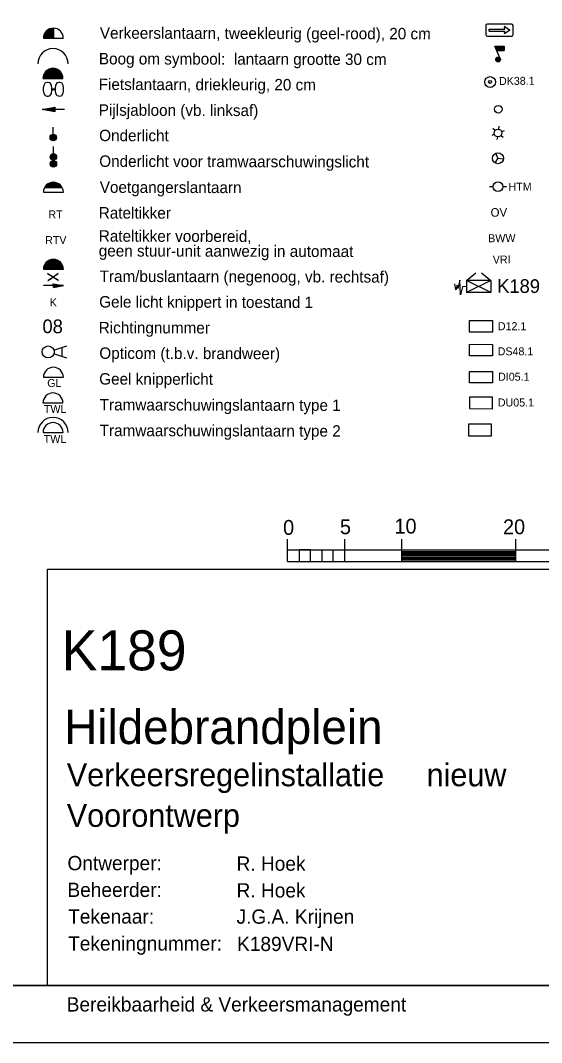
# Model space of a CAD drawing. Extents: x 81065 to 81486, y 452384 to 452681.
# Drawn here: x 81384.6 to 81430.3, y 452383.5 to 452473.1 of the extents above; entities that cross this region are included whole.
import ezdxf

# ---------------------------------------------------------------- set-up
doc = ezdxf.new("R2010")
doc.units = 0
for name, color, linetype in [('X-XX-AL-TEKENBLAD-S', 7, 'Continuous'), ('X-XX-AL-TEKENBLAD_KADER-G', 7, 'Continuous'), ('X-XX-AL-TEKENBLAD_KADER_AFSNIJMARKERING-G', 7, 'Continuous'), ('X-XX-AL-TEKENBLAD_VERKLARING-T70', 7, 'Continuous'), ('X-XX-AL-TEKENBLAD_VIEWPORT-G', 7, 'Continuous')]:
    doc.layers.add(name, color=color, linetype=linetype)

msp = doc.modelspace()

# ---------------------------------------------------------------- linework, layer by layer
at = {"layer": 'X-XX-AL-TEKENBLAD-S'}
for p, q in [((81408.052, 452425.679), (81408.05, 452427.626)), ((81413.05, 452425.679), (81413.05, 452427.626)), ((81418.05, 452425.679), (81418.05, 452427.626)), ((81428.05, 452425.679), (81428.05, 452427.626)), ((81408.053, 452426.679), (81458.05, 452426.679)), ((81410.05, 452426.679), (81409.05, 452426.679)), ((81409.05, 452426.679), (81409.05, 452425.679)), ((81410.05, 452425.679), (81410.05, 452426.679)), ((81411.05, 452426.679), (81411.05, 452425.679)), ((81412.05, 452425.679), (81412.05, 452426.679)), ((81418.05, 452426.553), (81428.05, 452426.553)), ((81418.05, 452426.429), (81428.05, 452426.429)), ((81408.053, 452425.679), (81458.05, 452425.679)), ((81418.05, 452426.303), (81428.05, 452426.303)), ((81418.05, 452426.179), (81428.05, 452426.179)), ((81418.05, 452426.053), (81428.05, 452426.053)), ((81418.05, 452425.929), (81428.05, 452425.929)), ((81418.05, 452425.803), (81428.05, 452425.803)), ((81418.05, 452425.679), (81428.05, 452425.679)), ((81387.021, 452388.532), (81387.021, 452424.987)), ((81387.021, 452424.987), (81480.708, 452424.987)), ((81387.021, 452388.532), (81480.708, 452388.532))]:
    msp.add_line(p, q, dxfattribs=at)
at = {"layer": 'X-XX-AL-TEKENBLAD_KADER-G'}
msp.add_lwpolyline([(81480.708, 452388.532), (81070.22, 452388.532), (81070.22, 452675.532), (81480.708, 452675.532)], close=True, dxfattribs=at)
at = {"layer": 'X-XX-AL-TEKENBLAD_KADER_AFSNIJMARKERING-G'}
msp.add_lwpolyline([(81485.714, 452680.532), (81065.214, 452680.532), (81065.214, 452383.532), (81485.714, 452383.532)], close=True, dxfattribs=at)
at = {"layer": 'X-XX-AL-TEKENBLAD_VERKLARING-T70'}
for p, q in [((81386.804, 452471.992), (81387.533, 452471.993)), ((81386.824, 452472.023), (81387.532, 452472.023)), ((81386.848, 452472.053), (81387.535, 452472.053)), ((81386.87, 452472.083), (81387.532, 452472.083)), ((81386.899, 452472.112), (81387.533, 452472.112)), ((81386.929, 452472.143), (81387.535, 452472.143)), ((81386.96, 452472.173), (81387.532, 452472.173)), ((81386.999, 452472.205), (81387.533, 452472.205)), ((81387.038, 452472.233), (81387.533, 452472.235)), ((81387.088, 452472.265), (81387.533, 452472.265)), ((81387.14, 452472.293), (81387.533, 452472.295)), ((81387.208, 452472.323), (81387.532, 452472.325)), ((81387.296, 452472.353), (81387.535, 452472.355)), ((81387.47, 452472.383), (81387.533, 452472.385)), ((81387.533, 452472.386), (81387.532, 452471.513)), ((81425.411, 452472.603), (81425.411, 452471.814)), ((81427.652, 452472.743), (81425.551, 452472.743)), ((81425.694, 452472.13), (81425.699, 452472.282)), ((81425.694, 452472.13), (81427.084, 452472.132)), ((81425.699, 452472.282), (81427.082, 452472.284)), ((81427.082, 452472.284), (81427.037, 452472.485)), ((81427.038, 452471.934), (81427.084, 452472.132)), ((81427.083, 452472.516), (81427.492, 452472.233)), ((81427.492, 452472.184), (81427.084, 452471.902)), ((81427.496, 452472.187), (81427.496, 452472.187)), ((81427.796, 452471.809), (81427.792, 452472.603)), ((81386.66, 452471.543), (81387.533, 452471.543)), ((81386.66, 452471.513), (81388.408, 452471.513)), ((81386.662, 452471.573), (81387.532, 452471.575)), ((81386.665, 452471.603), (81387.533, 452471.605)), ((81386.668, 452471.633), (81387.533, 452471.635)), ((81386.674, 452471.665), (81387.533, 452471.663)), ((81386.678, 452471.693), (81387.533, 452471.693)), ((81386.684, 452471.722), (81387.533, 452471.723)), ((81386.695, 452471.755), (81387.533, 452471.753)), ((81386.702, 452471.783), (81387.535, 452471.783)), ((81386.713, 452471.813), (81387.533, 452471.813)), ((81386.723, 452471.843), (81387.532, 452471.843)), ((81386.737, 452471.873), (81387.535, 452471.873)), ((81386.753, 452471.902), (81387.533, 452471.902)), ((81386.767, 452471.933), (81387.532, 452471.933)), ((81386.785, 452471.963), (81387.535, 452471.963)), ((81425.55, 452471.674), (81427.655, 452471.669)), ((81426.672, 452469.737), (81426.189, 452470.798)), ((81426.189, 452470.798), (81427.006, 452470.798)), ((81426.192, 452470.787), (81427.006, 452470.787)), ((81426.201, 452470.766), (81427.006, 452470.765)), ((81426.213, 452470.744), (81427.006, 452470.744)), ((81426.223, 452470.723), (81427.006, 452470.72)), ((81426.232, 452470.7), (81427.006, 452470.7)), ((81426.244, 452470.681), (81427.006, 452470.679)), ((81426.253, 452470.658), (81427.006, 452470.657)), ((81426.264, 452470.636), (81427.005, 452470.636)), ((81426.273, 452470.613), (81427.006, 452470.613)), ((81426.283, 452470.592), (81427.006, 452470.592)), ((81426.292, 452470.571), (81427.008, 452470.57)), ((81426.303, 452470.549), (81427.006, 452470.549)), ((81426.312, 452470.528), (81427.005, 452470.526)), ((81426.322, 452470.505), (81427.006, 452470.505)), ((81426.331, 452470.484), (81427.006, 452470.483)), ((81426.342, 452470.463), (81427.006, 452470.462)), ((81426.352, 452470.441), (81427.008, 452470.439)), ((81426.361, 452470.418), (81427.006, 452470.417)), ((81427.006, 452470.798), (81427.006, 452470.417)), ((81386.732, 452468.405), (81388.262, 452468.405)), ((81386.749, 452468.435), (81388.249, 452468.435)), ((81386.77, 452468.467), (81388.228, 452468.465)), ((81386.789, 452468.497), (81388.207, 452468.495)), ((81386.813, 452468.527), (81388.186, 452468.525)), ((81386.836, 452468.557), (81388.159, 452468.555)), ((81386.863, 452468.587), (81388.132, 452468.587)), ((81386.896, 452468.615), (81388.105, 452468.617)), ((81386.926, 452468.647), (81388.069, 452468.647)), ((81386.965, 452468.677), (81388.031, 452468.677)), ((81387.004, 452468.705), (81387.994, 452468.705)), ((81387.053, 452468.737), (81387.944, 452468.738)), ((81387.106, 452468.767), (81387.889, 452468.767)), ((81387.173, 452468.797), (81387.823, 452468.797)), ((81387.262, 452468.827), (81387.736, 452468.827)), ((81387.436, 452468.855), (81387.565, 452468.857)), ((81386.626, 452468.015), (81388.372, 452468.015)), ((81386.626, 452467.985), (81388.373, 452467.987)), ((81386.627, 452468.045), (81388.369, 452468.047)), ((81386.632, 452468.075), (81388.367, 452468.077)), ((81386.633, 452468.105), (81388.364, 452468.107)), ((81386.639, 452468.137), (81388.358, 452468.137)), ((81386.645, 452468.167), (81388.354, 452468.167)), ((81386.65, 452468.197), (81388.345, 452468.197)), ((81386.66, 452468.227), (81388.337, 452468.227)), ((81386.668, 452468.255), (81388.33, 452468.257)), ((81386.678, 452468.288), (81388.318, 452468.288)), ((81386.69, 452468.315), (81388.306, 452468.315)), ((81386.702, 452468.345), (81388.295, 452468.344)), ((81386.716, 452467.403), (81386.846, 452467.61)), ((81386.719, 452468.375), (81388.279, 452468.377)), ((81386.846, 452467.61), (81386.978, 452467.661)), ((81386.978, 452467.661), (81387.068, 452467.658)), ((81387.068, 452467.658), (81387.2, 452467.612)), ((81387.2, 452467.612), (81387.331, 452467.403)), ((81387.752, 452467.403), (81387.884, 452467.612)), ((81387.884, 452467.612), (81388.012, 452467.663)), ((81388.012, 452467.663), (81388.102, 452467.66)), ((81388.102, 452467.66), (81388.234, 452467.612)), ((81388.234, 452467.612), (81388.367, 452467.4)), ((81386.672, 452466.934), (81386.674, 452467.139)), ((81386.714, 452466.665), (81386.672, 452466.934)), ((81386.674, 452467.139), (81386.716, 452467.403)), ((81386.846, 452466.458), (81386.714, 452466.665)), ((81387.329, 452466.668), (81387.2, 452466.458)), ((81387.359, 452466.923), (81387.329, 452466.668)), ((81387.331, 452467.403), (81387.361, 452467.141)), ((81387.361, 452467.141), (81387.359, 452466.923)), ((81387.362, 452467.013), (81387.707, 452467.012)), ((81387.365, 452467.076), (81387.71, 452467.078)), ((81387.706, 452466.931), (81387.707, 452467.136)), ((81387.748, 452466.665), (81387.706, 452466.931)), ((81387.707, 452467.136), (81387.752, 452467.403)), ((81387.88, 452466.461), (81387.748, 452466.665)), ((81388.363, 452466.665), (81388.235, 452466.458)), ((81388.397, 452466.92), (81388.363, 452466.665)), ((81388.367, 452467.4), (81388.397, 452467.139)), ((81388.397, 452467.139), (81388.397, 452466.92)), ((81386.978, 452466.41), (81386.846, 452466.458)), ((81387.068, 452466.41), (81386.978, 452466.41)), ((81387.2, 452466.458), (81387.068, 452466.41)), ((81388.012, 452466.413), (81387.88, 452466.461)), ((81388.105, 452466.412), (81388.012, 452466.413)), ((81388.235, 452466.458), (81388.105, 452466.412)), ((81386.548, 452465.249), (81387.656, 452465.452)), ((81388.52, 452465.246), (81386.548, 452465.249)), ((81387.65, 452465.045), (81386.548, 452465.249)), ((81387.653, 452465.35), (81386.735, 452465.269)), ((81387.653, 452465.161), (81386.746, 452465.234)), ((81387.458, 452465.356), (81387.458, 452465.156)), ((81387.553, 452465.381), (81387.553, 452465.119)), ((81387.656, 452465.452), (81387.65, 452465.045)), ((81387.529, 452463.094), (81387.528, 452463.704)), ((81426.165, 452463.086), (81425.927, 452462.996)), ((81426.22, 452463.422), (81426.023, 452463.583)), ((81426.538, 452463.542), (81426.58, 452463.794)), ((81426.801, 452463.326), (81427.04, 452463.417)), ((81426.429, 452462.871), (81426.387, 452462.619)), ((81426.747, 452462.991), (81426.944, 452462.829)), ((81387.539, 452460.775), (81387.537, 452462.007)), ((81426.477, 452460.99), (81426.277, 452461.426)), ((81426.477, 452460.99), (81426.199, 452460.598)), ((81426.477, 452460.99), (81426.955, 452460.944)), ((81386.847, 452458.553), (81388.22, 452458.552)), ((81386.873, 452458.583), (81388.196, 452458.582)), ((81386.9, 452458.612), (81388.169, 452458.613)), ((81386.93, 452458.642), (81388.14, 452458.645)), ((81386.963, 452458.673), (81388.106, 452458.673)), ((81386.999, 452458.705), (81388.068, 452458.703)), ((81387.041, 452458.732), (81388.028, 452458.732)), ((81387.087, 452458.763), (81387.981, 452458.763)), ((81387.143, 452458.793), (81387.926, 452458.795)), ((81387.209, 452458.823), (81387.858, 452458.823)), ((81387.299, 452458.853), (81387.77, 452458.853)), ((81386.66, 452458.012), (81388.409, 452458.013)), ((81386.769, 452458.432), (81388.299, 452458.432)), ((81386.786, 452458.462), (81388.283, 452458.462)), ((81386.804, 452458.492), (81388.265, 452458.492)), ((81386.826, 452458.523), (81388.244, 452458.522)), ((81426.059, 452458.489), (81425.74, 452458.479)), ((81426.908, 452458.517), (81427.227, 452458.527)), ((81386.674, 452451.41), (81388.394, 452451.409)), ((81386.68, 452451.439), (81388.388, 452451.44)), ((81386.687, 452451.469), (81388.381, 452451.47)), ((81386.695, 452451.499), (81388.375, 452451.499)), ((81386.704, 452451.529), (81388.364, 452451.529)), ((81386.713, 452451.56), (81388.354, 452451.56)), ((81386.725, 452451.589), (81388.343, 452451.589)), ((81386.738, 452451.619), (81388.33, 452451.617)), ((81386.753, 452451.647), (81388.315, 452451.649)), ((81386.768, 452451.677), (81388.3, 452451.679)), ((81386.786, 452451.709), (81388.283, 452451.707)), ((81386.804, 452451.739), (81388.264, 452451.737)), ((81386.825, 452451.769), (81388.244, 452451.767)), ((81386.848, 452451.799), (81388.22, 452451.797)), ((81386.872, 452451.829), (81388.195, 452451.829)), ((81386.9, 452451.859), (81388.169, 452451.859)), ((81386.93, 452451.887), (81388.139, 452451.89)), ((81386.962, 452451.919), (81388.105, 452451.919)), ((81386.999, 452451.95), (81388.069, 452451.95)), ((81387.04, 452451.977), (81388.028, 452451.977)), ((81387.088, 452452.009), (81387.98, 452452.01)), ((81387.142, 452452.039), (81387.926, 452452.04)), ((81387.209, 452452.069), (81387.857, 452452.069)), ((81387.298, 452452.099), (81387.77, 452452.099)), ((81386.66, 452451.259), (81388.409, 452451.259)), ((81386.662, 452451.289), (81388.406, 452451.289)), ((81386.663, 452451.319), (81388.405, 452451.32)), ((81386.666, 452451.347), (81388.402, 452451.349)), ((81386.669, 452451.377), (81388.399, 452451.38)), ((81423.732, 452450.28), (81424.54, 452450.965)), ((81425.045, 452450.966), (81425.855, 452450.279)), ((81388.408, 452449.834), (81386.657, 452449.831)), ((81387.53, 452449.999), (81388.408, 452449.834)), ((81387.532, 452449.661), (81387.53, 452449.999)), ((81387.53, 452449.918), (81388.244, 452449.844)), ((81387.531, 452449.751), (81388.244, 452449.82)), ((81387.532, 452449.661), (81388.408, 452449.834)), ((81423.132, 452450.305), (81422.969, 452449.59)), ((81423.179, 452449.014), (81423.132, 452450.305)), ((81423.357, 452449.735), (81423.179, 452449.014)), ((81423.731, 452449.748), (81423.357, 452449.735)), ((81423.732, 452450.28), (81423.73, 452449.217)), ((81425.855, 452450.279), (81423.73, 452449.217)), ((81425.855, 452450.279), (81423.732, 452450.28)), ((81425.857, 452449.218), (81423.732, 452450.28)), ((81425.855, 452450.279), (81425.857, 452449.218)), ((81425.857, 452449.218), (81423.731, 452449.217)), ((81423.99, 452446.769), (81425.991, 452446.767)), ((81423.99, 452445.769), (81423.99, 452446.769)), ((81425.991, 452446.767), (81425.99, 452445.768)), ((81425.99, 452445.768), (81423.99, 452445.769)), ((81387.581, 452444.184), (81388.707, 452444.551)), ((81388.308, 452443.621), (81388.307, 452444.421)), ((81423.99, 452444.691), (81425.991, 452444.689)), ((81423.99, 452443.691), (81423.99, 452444.691)), ((81425.991, 452444.689), (81425.99, 452443.69)), ((81388.708, 452443.49), (81387.581, 452443.858)), ((81425.99, 452443.69), (81423.99, 452443.691)), ((81386.659, 452441.806), (81388.409, 452441.809)), ((81423.99, 452442.318), (81425.991, 452442.316)), ((81423.99, 452441.318), (81423.99, 452442.318)), ((81425.991, 452442.316), (81425.99, 452441.317)), ((81425.99, 452441.317), (81423.99, 452441.318)), ((81425.982, 452440.053), (81423.981, 452440.055)), ((81423.981, 452440.055), (81423.982, 452439.055)), ((81425.982, 452439.054), (81425.982, 452440.053)), ((81386.623, 452439.555), (81388.373, 452439.56)), ((81423.982, 452439.055), (81425.982, 452439.054)), ((81425.896, 452437.686), (81423.895, 452437.688)), ((81423.895, 452437.688), (81423.895, 452436.688)), ((81425.895, 452436.687), (81425.896, 452437.686)), ((81386.629, 452436.963), (81388.379, 452436.968)), ((81423.895, 452436.688), (81425.895, 452436.687))]:
    msp.add_line(p, q, dxfattribs=at)
msp.add_lwpolyline([(81422.969, 452449.59), (81422.914, 452449.859), (81422.798, 452449.453), (81422.688, 452449.987)], dxfattribs=at)
for centre, radius in [((81426.489, 452469.639), 0.207), ((81426.489, 452469.639), 0.185), ((81426.489, 452469.639), 0.164), ((81426.489, 452469.639), 0.142), ((81426.489, 452469.639), 0.12), ((81426.489, 452469.639), 0.0986), ((81426.489, 452469.639), 0.0769), ((81426.489, 452469.639), 0.0552), ((81426.489, 452469.639), 0.0335), ((81426.489, 452469.639), 0.0119), ((81425.789, 452467.665), 0.475), ((81425.787, 452467.671), 0.128), ((81426.499, 452465.283), 0.335), ((81387.527, 452462.799), 0.286), ((81387.527, 452462.799), 0.256), ((81387.527, 452462.799), 0.226), ((81426.483, 452463.206), 0.34), ((81387.527, 452462.799), 0.196), ((81387.527, 452462.799), 0.166), ((81387.527, 452462.799), 0.136), ((81387.527, 452462.799), 0.106), ((81387.527, 452462.799), 0.0765), ((81387.527, 452462.799), 0.0465), ((81387.527, 452462.799), 0.0165), ((81387.536, 452461.102), 0.286), ((81387.536, 452461.102), 0.256), ((81387.536, 452461.102), 0.226), ((81387.536, 452461.102), 0.196), ((81387.536, 452461.102), 0.166), ((81387.536, 452461.102), 0.136), ((81426.477, 452460.99), 0.48), ((81387.534, 452460.491), 0.286), ((81387.534, 452460.491), 0.256), ((81387.534, 452460.491), 0.226), ((81387.534, 452460.491), 0.196), ((81387.534, 452460.491), 0.166), ((81387.534, 452460.491), 0.136), ((81387.534, 452460.491), 0.106), ((81387.536, 452461.102), 0.106), ((81387.534, 452460.491), 0.0765), ((81387.536, 452461.102), 0.0765), ((81387.534, 452460.491), 0.0465), ((81387.536, 452461.102), 0.0465), ((81387.534, 452460.491), 0.0165), ((81387.536, 452461.102), 0.0165), ((81426.483, 452458.503), 0.425), ((81387.081, 452444.021), 0.526)]:
    msp.add_circle(centre, radius, dxfattribs=at)
for centre, radius, start, end in [((81387.533, 452471.512), 0.873, 359.99975, 179.99975), ((81425.551, 452472.603), 0.14, 89.99975, 179.99975), ((81427.066, 452472.491), 0.03, 55.3263, 192.52856), ((81427.475, 452472.209), 0.03, 304.64413, 55.3263), ((81427.652, 452472.603), 0.14, 0.2932, 89.99975), ((81425.551, 452471.814), 0.14, 179.99975, 269.86262), ((81427.067, 452471.927), 0.03, 167.00514, 304.64413), ((81427.656, 452471.809), 0.14, 269.86262, 0.2932), ((81387.502, 452469.269), 1.323, 359.99975, 179.99975), ((81387.498, 452467.986), 0.873, 359.99975, 179.99975), ((81387.534, 452458.013), 0.873, 359.99975, 179.99975), ((81387.534, 452451.259), 0.873, 359.99975, 179.99975), ((81387.535, 452441.806), 0.873, 359.99975, 179.99975), ((81387.498, 452439.557), 0.873, 359.99975, 179.99975), ((81387.505, 452436.965), 1.323, 359.99975, 179.99975), ((81387.505, 452436.965), 0.873, 359.99975, 179.99975)]:
    msp.add_arc(centre, radius, start, end, dxfattribs=at)
at = {"layer": 'X-XX-AL-TEKENBLAD_VIEWPORT-G'}
msp.add_lwpolyline([(81070.22, 452388.532), (81480.708, 452388.532), (81480.708, 452675.532), (81070.22, 452675.532)], close=True, dxfattribs=at)

# ---------------------------------------------------------------- texts
at = {"layer": 'X-XX-AL-TEKENBLAD-S'}
for s, height, p in [('0', 1.3, (81407.656, 452428.003)), ('5', 1.3, (81412.633, 452428.06)), ('10', 1.3, (81417.41, 452428.116)), ('20', 1.3, (81426.918, 452428.058)), ('Hildebrandplein', 3, (81388.484, 452409.678)), ('Verkeersregelinstallatie     nieuw', 2, (81388.712, 452405.982)), ('Voorontwerp', 2, (81388.712, 452402.425)), ('Ontwerper:', 1.25, (81388.767, 452398.625)), ('R. Hoek', 1.25, (81403.578, 452398.58)), ('Beheerder:', 1.25, (81388.767, 452396.283)), ('R. Hoek', 1.25, (81403.578, 452396.238)), ('Tekenaar:', 1.25, (81388.829, 452393.946)), ('J.G.A. Krijnen', 1.25, (81403.578, 452393.938)), ('Tekeningnummer:', 1.25, (81388.829, 452391.588)), ('K189VRI-N', 1.25, (81403.626, 452391.547)), ('Bereikbaarheid & Verkeersmanagement', 1.25, (81388.705, 452386.25))]:
    msp.add_text(s, height=height, dxfattribs=at).set_placement(p)
msp.add_text('K189', height=3.5, rotation=359.97986, dxfattribs=at).set_placement((81388.268, 452416.137))
at = {"layer": 'X-XX-AL-TEKENBLAD_VERKLARING-T70'}
for s, height, rotation, p in [('Verkeerslantaarn, tweekleurig (geel-rood), 20 cm', 1, 359.86856, (81391.607, 452471.465)), ('Boog om symbool:  lantaarn grootte 30 cm', 1, 359.86856, (81391.52, 452469.212)), ('Fietslantaarn, driekleurig, 20 cm', 1, 359.86856, (81391.504, 452466.969)), ('DK38.1', 0.7, 0.48311, (81426.566, 452467.402)), ('Pijlsjabloon (vb. linksaf)', 1, 359.86856, (81391.513, 452464.714)), ('Onderlicht', 1, 359.86856, (81391.548, 452462.488)), ('Onderlicht voor tramwaarschuwingslicht', 1, 359.86856, (81391.551, 452460.234)), ('Voetgangerslantaarn', 1, 359.86856, (81391.598, 452457.96)), ('HTM', 0.7, 0.48311, (81427.401, 452458.133)), ('Rateltikker', 1, 359.86856, (81391.51, 452455.712)), ('RT', 0.7, 0.48311, (81387.099, 452455.721)), ('OV', 0.75, 0.48311, (81425.831, 452455.866)), ('RTV', 0.7, 0.48311, (81386.815, 452453.463)), ('Rateltikker voorbereid,', 1, 359.86856, (81391.512, 452453.683)), ('BWW', 0.7, 0.48311, (81425.62, 452453.627)), ('geen stuur-unit aanwezig in automaat', 1, 359.86856, (81391.51, 452452.388)), ('VRI', 0.7, 0.48311, (81426.025, 452451.761)), ('x', 1.26, 271.49975, (81387.005, 452450.987)), ('Tram/buslantaarn (negenoog, vb. rechtsaf)', 1, 359.86856, (81391.58, 452450.156)), ('K189', 1.2, 359.6614, (81426.403, 452449.206)), ('K', 0.7, 0.48311, (81387.217, 452448.009)), ('Gele licht knippert in toestand 1', 1, 359.86856, (81391.546, 452447.916)), ('08', 1.2, 359.6614, (81386.576, 452445.672)), ('Richtingnummer', 1, 359.86856, (81391.506, 452445.66)), ('D12.1', 0.7, 359.99975, (81426.464, 452445.93)), ('Opticom (t.b.v. brandweer)', 1, 359.86856, (81391.558, 452443.421)), ('DS48.1', 0.7, 359.99975, (81426.449, 452443.727)), ('GL', 0.7, 0.48311, (81386.999, 452440.949)), ('Geel knipperlicht', 1, 359.86856, (81391.549, 452441.165)), ('DI05.1', 0.7, 359.99975, (81426.483, 452441.502)), ('Tramwaarschuwingslantaarn type 1', 1, 359.86856, (81391.592, 452438.904)), ('DU05.1', 0.7, 359.99975, (81426.464, 452439.247)), ('TWL', 0.7, 0.48311, (81386.709, 452438.668)), ('Tramwaarschuwingslantaarn type 2', 1, 359.86856, (81391.591, 452436.651)), ('TWL', 0.7, 0.48311, (81386.691, 452436.045))]:
    msp.add_text(s, height=height, rotation=rotation, dxfattribs=at).set_placement(p)

doc.saveas('drawing.dxf')
